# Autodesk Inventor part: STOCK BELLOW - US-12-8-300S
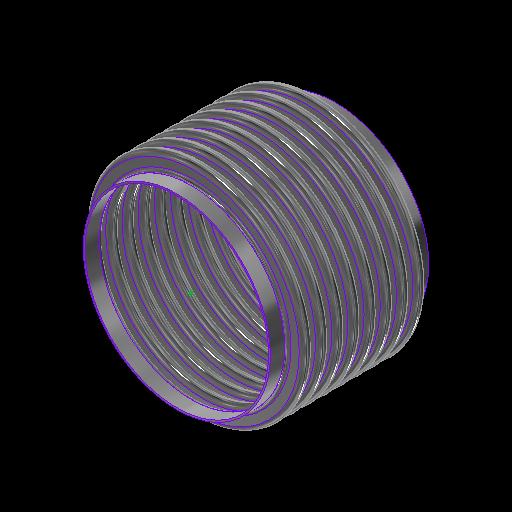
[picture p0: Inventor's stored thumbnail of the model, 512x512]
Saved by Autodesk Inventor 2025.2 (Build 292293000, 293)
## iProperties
Category: 16 GA (0.060 THICK)
RuleStatus: InUse
Created: 2024-01
Part Number: STOCK BELLOW - US-12-8-300S
Project: =STOCK BELLOWS: <Stock Number><SFILL>
Material: ASTM A240-304
Description: =STOCK BELLOWS: <Stock Number>, <SID_> I.D., <SOD_> O.D., <SPLY_> PLY, <Category>, <SNET_CONS> CONS.<PITCH_><STANGENT_> TANGENT<SFILL>
Document SubType Name: Sheet Metal
Designer: GS
Stock Number: U.S-12-8-300S
Surface Area: 14407.3 cm^2
Volume: 2167.04 cm^3
Sheet Metal Rule: Default
Appearance: STAINLESS STEEL
Mass: 17460.5 g
Density: 8.05729 g/cm^3
THK: 0.036
ID: 3.500
OD: 4.250
CONS_: 2
PITCH: 0.500
TANGENT: 0.500
BELLOWS_UPSET: 0.000
d79: 1.000
d82: 1.000
d83: 26.000
d84: 24.000
d174: 8
d214: 8
STHK_: 0.060
SID_: 12.750
SOD_: 15.250
SPITCH_: 1.125
STANGENT__: 1.000
SBELLOWS_UPSET_: 0.000
SDIFF_TAN: 1.000
d252: 2
d275: 2
d287: 0.050
d289: 0.500
d290: 0.000
SOD_NECK: 13
PLY: 1
PSET: 4.178
PBAR: 1.035
COUNTER: 1.500
NET_TUBE: 3.071
CONS: 2
S_CONS: 0
NET_CONS: 2
ID_M: 88.90 mm
OD_M: 107.95 mm
THK_M: 0.91 mm
ID_U: 3.500 in
OD_U: 4.250 in
THK_U: 0.036 in
TANGENT2: 0.500
TAN_TO_TAN: 1.000 in
d80: 2.571
d81: 10
SID: 2.375
SCONS_: 8
SPITCH: 0.250
STANGENT_: 1.000
SBELLOWS_UPSET: 0.000
SNET_CONS: 8
SS_CONS: 0
SCONS: 8
d190: 8
d191: 1
d192: 1
d193: 8
d194: 0
SIZE: 12.00
PRESSURE: 300
d230: 8
STANGENT: 4.000
SPLY_: 2
d233: 8
d234: 0
d263: 2
d265: 1
d268: 2
d269: 0
d286: 2
d288: 1
d291: 2
d292: 0
SREROLL: 0.750
BLETP: 0.000 ul
PRES_Copy: 85
MATTABLE: 20 GA (0.036 THICK)
PART_NUMBER: U.S-12-8-300S
PITCH_: =, <SPITCH_> PITCH,
CFILL: .
SFILL: .
MESH: ,
COMP: 1.57
EXT: 0.79
LAT: 0.33
ANG: 573
ASR: 7424
LSR: 26948
ANSR: 3175
PRES: 300
COMPM: 15.7
EXTM: 7.85
LATM: 3.30
ASRM: 1300.165
PRESM: 20.684
LSRM: 4719.403
ANSRM: 556.038
TEMPMIN: 20
TEMPMAX: 800
TEMPMINM: -7
TEMPMAXM: 427
WEIGHTM: 17.460
WEIGHT: 38.494
Author: GS
Keywords: 20 GA (0.036 THICK)
Comments: =STOCK BELLOW - <STOCK NUMBER>
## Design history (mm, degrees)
sketch "Sketch2"
  geometry: L1 (0, -177.245)-(0, 562.856) reference; L2 (45.364, 0)-(44.45, 0); L3 (48.082, -2.718)-(50.343, -2.718); L4 (48.082, -3.632)-(50.343, -3.632); L5 (50.343, -9.982)-(48.082, -9.982); L6 (50.343, -9.068)-(48.082, -9.068); L7 (45.364, -12.7)-(44.45, -12.7); L8 (48.082, 0)-(48.082, -12.7); L9 (50.343, -6.35)-(53.975, -6.35); L10 (44.45, 0)-(44.45, -12.7); L11 (20.376, 102.841)-(20.376, 101.926); L12 (58.262, 457.127)-(58.262, 349.177); L13 (58.262, 444.427)-(58.262, 336.477); L14 (93.133, -58.817)-(93.133, -71.517); L15 (118.746, -66.401)-(118.746, -66.401); L16 (50.343, -9.068)-(50.343, -9.982); L17 (48.082, -9.068)-(48.082, -9.982); L18 (48.082, -9.525)-(50.343, -9.525); L19 (53.975, 0)-(53.975, -12.7); L20 (-50.343, -9.068)-(-50.343, -9.982); L21 (-50.343, -2.718)-(-48.082, -2.718); L22 (-50.343, -3.632)-(-48.082, -3.632); L23 (-48.082, -9.068)-(-50.343, -9.068); L24 (-50.343, -9.525)-(-48.082, -9.525); L25 (-48.082, -9.982)-(-50.343, -9.982); L26 (-48.082, -9.068)-(-48.082, -9.982); L27 (-44.45, 0.653)-(-44.45, -12.047); L28 (-48.082, -6.35)-(-44.45, -6.35); L29 (-50.343, 0.653)-(-50.343, -12.7); L30 (-53.061, 0)-(-53.975, 0); L31 (-53.975, 0)-(-53.975, -12.7); L32 (-53.061, -12.7)-(-53.975, -12.7); A1 r 2.718 centre (48.082, 0) between (45.364, 0) and (48.082, -2.718); A2 r 3.632 centre (48.082, 0) between (44.45, 0) and (48.082, -3.632); A3 r 3.632 centre (50.343, -6.35) between (50.343, -9.982) and (50.343, -2.718); A4 r 2.718 centre (50.343, -6.35) between (50.343, -9.068) and (50.343, -3.632); A5 r 2.718 centre (48.082, -12.7) between (48.082, -9.982) and (45.364, -12.7); A6 r 3.632 centre (48.082, -12.7) between (48.082, -9.068) and (44.45, -12.7); A7 r 3.175 centre (50.343, -6.35) between (50.343, -9.525) and (53.518, -6.35); A8 r 3.175 centre (48.082, -12.7) between (48.082, -9.525) and (44.907, -12.7); A9 r 2.718 centre (-50.343, -12.7) between (-50.343, -9.982) and (-53.061, -12.7); A10 r 2.718 centre (-48.082, -6.35) between (-48.082, -9.068) and (-48.082, -3.632); A11 r 3.175 centre (-48.082, -6.35) between (-48.082, -9.525) and (-44.907, -6.35); A12 r 3.632 centre (-48.082, -6.35) between (-48.082, -9.982) and (-48.082, -2.718); A13 r 3.175 centre (-50.343, -12.7) between (-50.343, -9.525) and (-53.518, -12.7); A14 r 3.632 centre (-50.343, -12.7) between (-50.343, -9.068) and (-53.975, -12.7); A15 r 2.718 centre (-50.343, 0) between (-53.061, 0) and (-50.343, -2.718); A16 r 3.632 centre (-50.343, 0) between (-53.975, 0) and (-50.343, -3.632); 10 further points
  constraints: 62 end point, 38 point on circle, 20 tangent, 16 centre point, 12 parallel, 9 midpoint, 7 vertical, 6 coincident, 6 concentric, 6 point on line, 4 equal radius, 4 perpendicular, 3 horizontal, 1 collinear, 1 horizontal alignment, 10 other
  dimensions: "THK" = 0.9144 distance of L11.start L11.end; "ID" = 88.9 distance of L11.end point (20.376, 13.026); "OD" = 107.95 distance of L12.start L12.end; "PITCH" = 12.7 distance of L12.start L13.start; "TANGENT" = 12.7 distance of L14.start L14.end; "BELLOWS_UPSET" = 0 distance of L15.start L15.end; "d43" = 88.9 diameter of L10 L1 (= ID); "d44" = 107.95 diameter of L9.end L1 (= OD); "d45" = 0.9144 distance between parallel lines of L5 L6 (computed from THK, PLY); "d46" = 3.6322 radius of A3 (computed from PITCH, THK, PLY); "UPSET_PITCH" = 12.7 distance of L2.end L7.end (derived); "SIDEWALL_ANGLE" = 360 deg dimension on L3 L9 (derived); "CON_GAP" = 5.4356 distance of point (48.082, -9.068) point (48.082, -3.632) (derived); "TAN1" = 4.98728 dimension on A8 (derived); "TAN2" = 4.98728 dimension on A7 (derived); "LEG1" = 2.2606 distance of L18.start L18.end (derived); "d278" = 0.9144 distance between parallel lines of L25 L23 (derived); "d279" = 3.6322 radius of A12 (derived); "d280" = 12.7 distance of L30.end L31.end (derived); "d281" = 360 deg dimension on L21 L28 (derived); "d282" = 5.4356 distance of point (-50.343, -9.068) point (-50.343, -3.632) (derived); "d283" = 4.98728 dimension on A13 (derived); "d284" = 4.98728 dimension on A11 (derived); "d285" = 2.2606 distance of L24.start L24.end (derived); "d293" = 88.9 diameter of L27 L1 (derived); "d294" = 107.95 diameter of L31 L1 (derived)
  node "Sketch Rectangular Pattern1" dims "d31" = 25.4, "ID" = 88.9
  node "Sketch Rectangular Pattern2" dims "d39" = 25.4, "PITCH" = 12.7
revolve "CONS" stored, may be unused: angle "d48" = 90 deg
node "BELLOW MIDPLANE"
pattern_linear "Rectangular Pattern2" dims "d52" = 12.7 (= UPSET_PITCH)
sketch "Sketch5"
  geometry: C1 r 45.364 at (0, 0) reference; C2 r 44.45 at (0, 0) reference
extrude "TANGENT" new body sketch "Sketch5" distance "d53" = 12.7 (= TANGENT); taper "d54" = 0 deg
revolve "SAMETAN" stored, may be unused: angle "d65" = 90 deg
revolve "DIFFTAN" stored, may be unused: angle "d70" = 90 deg
sketch "Sketch9"
  geometry: L1 (53.319, 0)-(-53.319, 0) reference; L2 (0, -17.78)-(0, 17.78) reference; L3 (38.085, 0)-(-38.085, 0); L4 (38.085, -11.906)-(38.085, 11.906); L5 (25.385, -11.906)-(25.385, 11.906); L6 (13.15, 11.906)-(13.15, -11.906); L7 (-25.385, -11.906)-(-25.385, 11.906); L8 (-38.085, -11.906)-(-38.085, 11.906); L9 (37.291, -11.906)-(37.291, 11.906); L10 (38.085, -11.906)-(37.291, -11.906); L11 (38.085, 11.906)-(37.291, 11.906); L12 (13.546, 11.906)-(12.753, 11.906); L13 (12.753, 11.906)-(12.753, -11.906); L14 (12.753, -11.906)-(13.546, -11.906); L15 (13.546, -11.906)-(13.546, 11.906); L16 (-13.546, 11.906)-(-13.546, -11.906); L17 (-13.15, 11.906)-(-13.15, -11.906); L18 (-13.546, -11.906)-(-12.753, -11.906); L19 (-12.753, -11.906)-(-12.753, 11.906); L20 (-12.753, 11.906)-(-13.546, 11.906); L21 (-38.085, -11.906)-(-37.291, -11.906); L22 (-37.291, -11.906)-(-37.291, 11.906); L23 (-37.291, 11.906)-(-38.085, 11.906); L24 (-38.085, 11.906)-(-38.085, -11.906); L25 (38.085, -0.397)-(-38.085, -0.397); L26 (-38.085, -0.397)-(-38.085, 0.397); L27 (-38.085, 0.397)-(38.085, 0.397); L28 (38.085, 0.397)-(38.085, -0.397); L29 (-38.085, 11.906)-(38.085, 11.906); L30 (38.085, 11.906)-(38.085, 12.7); L31 (38.085, 12.7)-(-38.085, 12.7); L32 (-38.085, 12.7)-(-38.085, 11.906); L33 (38.085, -11.906)-(-38.085, -11.906); L34 (-38.085, -11.906)-(-38.085, -12.7); L35 (-38.085, -12.7)-(38.085, -12.7); L36 (38.085, -12.7)-(38.085, -11.906); 30 further points
  constraints: 68 end point, 13 midpoint, 13 parallel, 8 horizontal, 7 perpendicular, 6 equal length, 3 point on line, 2 vertical, 14 other
  dimensions: "d115" = 23.8125 distance of L4.start L4.end (derived); "d116" = 12.7 distance between parallel lines of L4 L5 (derived); "d117" = 12.23516 distance between parallel lines of L5 L6 (derived); "d125" = 38.53427 distance between parallel lines of L7 L6 (derived); "d127" = 12.7 distance between parallel lines of L8 L7 (derived); "d128" = 24.93516 distance between parallel lines of L6 L4 (derived); "d130" = 76.16943 distance between parallel lines of L8 L4 (derived); "RULER_THK" = 0.79375 distance between parallel lines of L4 L9; "d135" = 0.79375 distance of L13.end L14.end (derived); "d138" = 26.29911 distance of L13.end L16.end (derived); "d143" = 0.79375 distance of L22.end L8.end (derived); "d144" = 0.79375 distance between parallel lines of L27 L25 (derived)
extrude "RULER" join sketch "Sketch9" distance "d149" = 0.79375 (derived); taper "d150" = 0 deg
extrude "BARS" join sketch "Sketch9" distance "d151" = 0.79375 (derived); taper "d152" = 0 deg
pattern_linear "Rectangular Pattern4" dims "d155" = 26.29911 (derived)
sketch "Sketch13"
  geometry: L1 (93.149, -52.467)-(93.149, -77.867); L2 (164.973, 0)-(161.925, 0); L3 (164.973, -28.575)-(161.925, -28.575); L4 (185.007, -22.955)-(170.593, -22.955); L5 (185.007, -19.907)-(170.593, -19.907); L6 (185.007, -14.287)-(193.675, -14.288); L7 (170.593, -5.62)-(185.007, -5.62); L8 (170.593, 0)-(170.593, -28.575); L9 (161.925, 0)-(161.925, -28.575); L10 (58.254, -109.081)-(58.254, -496.431); L11 (58.254, -137.656)-(58.254, -525.006); L12 (58.254, -194.806)-(58.254, -582.156); L13 (58.254, -223.381)-(58.254, -610.731); L14 (58.254, -251.956)-(58.254, -639.306); L15 (58.254, -280.531)-(58.254, -667.881); L16 (58.254, -309.106)-(58.254, -696.456); L17 (58.254, -166.231)-(58.254, -553.581); L18 (20.376, 103.45)-(20.376, 101.926); L19 (170.593, -8.668)-(185.007, -8.668); L20 (0, -856.437)-(0, 263.431) reference; L21 (-38.735, 0)-(232.41, 0) reference; A1 r 5.62 centre (170.593, 0) between (164.973, 0) and (170.593, -5.62); A2 r 5.62 centre (170.593, -28.575) between (170.593, -22.955) and (164.973, -28.575); A3 r 8.668 centre (170.593, -28.575) between (170.593, -19.907) and (161.925, -28.575); A4 r 5.62 centre (185.007, -14.287) between (185.007, -19.907) and (185.007, -8.668); A5 r 8.668 centre (185.007, -14.287) between (185.007, -22.955) and (185.007, -5.62); A6 r 8.668 centre (170.593, 0) between (161.925, 0) and (170.593, -8.668); 6 further points; 1 other entity
  constraints: 38 end point, 15 point on circle, 9 tangent, 6 centre point, 6 parallel, 5 vertical alignment, 4 point on line, 4 vertical, 3 coincident, 3 concentric, 2 collinear, 2 equal radius, 1 horizontal, 1 perpendicular, 23 other
  dimensions: "SBELLOWS_UPSET_" = 0 distance of point (118.762, -66.401) point (118.762, -66.401); "STOTAL_THK_BELLOW__" = 3.048 distance between parallel lines of L4 L5 (derived); "d224" = 8.66775 radius of A5 (derived); "d225" = 28.575 distance of L2.end L3.end (derived); "SSIDEWALL_ANGLE_" = 360 deg dimension on L7 L6 (derived); "SSCON_GAP_" = 11.2395 distance of point (170.593, -19.907) point (170.593, -8.668) (derived); "d235" = 323.85 diameter of L9 L20 (derived); "d236" = 387.35 diameter of L6.end L20 (derived)
  node "Sketch Rectangular Pattern4" dims "d228" = 25.4
  node "Sketch Rectangular Pattern5" dims "d229" = 25.4
revolve "SBELLOW" stored, may be unused: angle "d197" = 90 deg
pattern_linear "Rectangular Pattern5" dims "d204" = 28.575 (derived)
revolve "STANGENT" stored, may be unused: angle "d240" = 90 deg
revolve "SSAMETAN" stored, may be unused: angle "d241" = 90 deg
revolve "SDIFFTAN" stored, may be unused: angle "d246" = 90 deg
revolve "INVCON" stored, may be unused: angle "d295" = 90 deg
pattern_linear "Rectangular Pattern6" dims "d298" = 12.7 (derived)
revolve "INVTANGENT" stored, may be unused: angle "d302" = 90 deg
revolve "INVSAMETAN" stored, may be unused: angle "d307" = 90 deg
revolve "INVDIFFTAN" stored, may be unused: angle "d312" = 90 deg
sketch "ID BELLOW MOUNT CALC"
  geometry: L1 (44.45, 0)-(38.1, 0); L2 (38.1, 0)-(38.1, 12.7); L3 (38.1, 12.7)-(44.45, 12.7); L4 (44.45, 12.7)-(44.45, 0); L5 (36.513, 12.7)-(35.598, 12.7); L6 (35.598, 12.7)-(35.598, 0); L7 (35.598, 0)-(36.513, 0); L8 (36.513, 0)-(36.513, 12.7); L9 (0, -2.54)-(0, 15.24) reference; L10 (-8.89, 0)-(53.34, 0) reference; 1 further point
  constraints: 16 end point, 5 parallel, 2 collinear, 2 horizontal, 2 perpendicular
  dimensions: "d314" = 12.7 distance of L5.end L6.end (derived); "d315" = 0.9144 distance of L5.start L5.end (derived); "IG" = 1.5875 distance between parallel lines of L2 L8; "PIPE_OD" = 88.9 diameter of L4 L9; "PIPE_WALL" = 6.35 distance of L2.end L3.end; "ID_MT_BELLOW" = 71.1962 diameter of L6 L9 (derived)
revolve "CFILL" stored, may be unused: angle "d320" = 90 deg
pattern_linear "Rectangular Pattern7" dims "d323" = 12.7 (derived)
revolve "SFILL" stored, may be unused: angle "d324" = 90 deg
pattern_linear "Rectangular Pattern8" dims "d327" = 28.575 (derived)
node "STOCK BELLOW MIDPLANE"
node "BELLOW"
sketch "Sketch6"
  geometry: L1 (-12.7, 45.364)-(0, 45.364); L2 (0, 45.364)-(0, 44.45); L3 (0, 44.45)-(-12.7, 44.45); L4 (-12.7, 44.45)-(-12.7, 45.364); L5 (10.16, 0)-(-60.96, 0) reference; L6 (-38.1, -89.422)-(-38.1, 153.44) reference; 1 further point
  constraints: 8 end point, 2 parallel, 1 horizontal, 1 perpendicular
  dimensions: "d61" = 12.7 distance of L2.end L3.end (derived); "d62" = 0.9144 distance of L1.end L2.end (derived); "d63" = 88.9 diameter of L3 L5 (derived); "d64" = 25.4 distance between parallel lines of L4 L6 (derived)
sketch "Sketch12"
  geometry: 1 further point
sketch "Sketch14"
  geometry: L1 (-25.4, 164.973)-(0, 164.973); L2 (0, 164.973)-(0, 161.925); L3 (0, 161.925)-(-25.4, 161.925); L4 (-25.4, 161.925)-(-25.4, 164.973); L5 (5.08, 0)-(-30.48, 0) reference; L6 (0, -32.995)-(0, 197.968) reference; 1 further point
  constraints: 8 end point, 2 parallel, 1 collinear, 1 horizontal, 1 perpendicular
  dimensions: "d237" = 3.048 distance of L3.end L1.start (derived); "d238" = 323.85 diameter of L3 L5 (derived); "d239" = 25.4 distance of L1.start L1.end (derived); "SOD_NECK" = 329.946 diameter of L1 L5 (derived)
sketch "Sketch15"
  geometry: L1 (-32.995, 0)-(197.968, 0) reference; L2 (161.925, -228.6)-(164.973, -228.6); L3 (164.973, -228.6)-(164.973, -254); L4 (164.973, -254)-(161.925, -254); L5 (161.925, -254)-(161.925, -228.6); L6 (0, -307.34)-(0, 66.04) reference; 1 further point
  constraints: 8 end point, 2 parallel, 1 horizontal, 1 perpendicular
  dimensions: "d205" = 25.4 distance of L4.end L2.start (derived); "d206" = 3.048 distance of L3.end L4.end (derived); "d207" = 323.85 diameter of L5 L6 (derived); "d208" = 228.6 distance between parallel lines of L1 L2 (derived)
node "TANGENT_"
node "SAME_TAN"
sketch "Sketch8"
  geometry: L1 (45.364, -25.4)-(44.45, -25.4); L2 (44.45, -25.4)-(44.45, -38.1); L3 (44.45, -38.1)-(45.364, -38.1); L4 (45.364, -38.1)-(45.364, -25.4); L5 (0, -48.26)-(0, 22.86) reference; L6 (-89.422, 0)-(153.44, 0) reference; 1 further point
  constraints: 8 end point, 2 parallel, 1 horizontal, 1 perpendicular
  dimensions: "d66" = 88.9 diameter of L2 L5 (derived); "TOTAL_THK_BELLOW" = 0.9144 distance of L2.end L3.end (derived); "d68" = 25.4 distance between parallel lines of L1 L6 (derived); "d69" = 12.7 distance of L1.end L2.end (derived)
node "DIFF_TAN"
node "Sketch Rectangular Pattern3" dims "d138" = 26.29911 (derived), "d141" = 25.4
node "SBELLOW_"
node "STANGENT_"
node "SSAME_TAN"
sketch "Sketch16"
  geometry: L1 (164.973, -228.6)-(161.925, -228.6); L2 (161.925, -228.6)-(161.925, -254); L3 (161.925, -254)-(164.973, -254); L4 (164.973, -254)-(164.973, -228.6); L5 (0, -307.34)-(0, 66.04) reference; L6 (-32.995, 0)-(197.968, 0) reference; 1 further point
  constraints: 8 end point, 2 parallel, 1 horizontal, 1 perpendicular
  dimensions: "SDIFF_TAN" = 25.4 distance of L3.end L1.start; "d243" = 3.048 distance of L2.end L3.end (derived); "d244" = 228.6 distance between parallel lines of L1 L6 (derived); "d245" = 323.85 diameter of L2 L5 (derived)
node "SDIFF_TAN"
body "Solid15"
sketch "Sketch17"
  geometry: L1 (53.975, 12.7)-(53.061, 12.7); L2 (53.061, 12.7)-(53.061, 0); L3 (53.061, 0)-(53.975, 0); L4 (53.975, 0)-(53.975, 12.7); L5 (0, -2.54)-(0, 15.24) reference; L6 (-10.795, 0)-(64.77, 0) reference; 2 further points
  constraints: 8 end point, 2 parallel, 1 horizontal, 1 midpoint, 1 perpendicular, 1 point on line
  dimensions: "INVTANGENT" = 12.7 distance of L3.end L1.start (derived); "d300" = 0.9144 distance of L1.start L1.end (derived); "d301" = 107.95 diameter of L4 L5 (derived)
body "Solid16"
sketch "Sketch18"
  geometry: L1 (53.975, -25.4)-(53.061, -25.4); L2 (53.061, -25.4)-(53.061, -38.1); L3 (53.061, -38.1)-(53.975, -38.1); L4 (53.975, -38.1)-(53.975, -25.4); L5 (-10.795, 0)-(64.77, 0) reference; L6 (0, -48.26)-(0, 22.86) reference; 1 further point
  constraints: 8 end point, 2 parallel, 1 horizontal, 1 perpendicular
  dimensions: "d303" = 25.4 distance between parallel lines of L1 L5 (derived); "d304" = 12.7 distance of L3.end L1.start (derived); "d305" = 0.9144 distance of L2.end L3.end (derived); "d306" = 107.95 diameter of L4 L6 (derived)
body "Solid17"
sketch "Sketch19"
  geometry: L1 (53.975, -25.4)-(53.061, -25.4); L2 (53.061, -25.4)-(53.061, -38.1); L3 (53.061, -38.1)-(53.975, -38.1); L4 (53.975, -38.1)-(53.975, -25.4); L5 (0, -48.26)-(0, 22.86) reference; L6 (-10.795, 0)-(64.77, 0) reference; 1 further point
  constraints: 8 end point, 2 parallel, 1 horizontal, 1 perpendicular
  dimensions: "d308" = 12.7 distance of L1.end L2.end (derived); "d309" = 107.95 diameter of L4 L5 (derived); "d310" = 0.9144 distance of L2.end L3.end (derived); "d311" = 25.4 distance between parallel lines of L1 L6 (derived)
body "Solid18"
body "Solid19"
body "Solid20"
other parameters: "BMPL" = -114.3, "PSET" = 106.1212 (computed from OD, THK, PLY) [user parameter], "PBAR" = 26.29911 (= 0.570796 x PITCH + OD - ID) [user parameter; used in 1 equation term], "COUNTER" = 15 [user parameter], "NET_TUBE" = 77.99823 (computed from CONS_, PBAR, TANGENT) [user parameter], "S_CONS" = 0 [user parameter; used in 1 equation term], "ID_M" = 88.9 (= ID) [user parameter], "OD_M" = 107.95 (= OD) [user parameter], "THK_M" = 0.9144 (= THK) [user parameter], "ID_U" = 88.9 (= ID) [user parameter], "OD_U" = 107.95 (= OD) [user parameter], "THK_U" = 0.9144 (= THK) [user parameter], "D_UNITS" = 0 [user parameter], "TANGENT2" = 12.7 [user parameter], "TAN_TO_TAN" = 25.4 [user parameter], "OD_NECK" = 90.7288 [user parameter], "d79" = 25.4, "d80" = 65.29823 [user parameter], "d82" = 25.4, "d83" = 660.4, "d84" = 609.6, "sa_0" = 4, "FRAME_THK" = 0.79375 [user parameter], "CON_FLAT" = 12.23516 [user parameter], "SID" = 60.325 [user parameter], "SPITCH" = 6.35 [user parameter], "STANGENT_" = 25.4 [user parameter], "SBELLOWS_UPSET" = 0 [user parameter], "SS_CONS" = 0 [user parameter], "STAN_TO_TAN_" = 228.6 [user parameter], "d100" = 3.048 [user parameter], "d191" = 25.4 [user parameter], "d194" = 0 [user parameter], "STANGENT" = 101.6 [user parameter], "d234" = 0 [user parameter], "SUPSET_PITCH_" = 28.575 [user parameter], "d269" = 0 [user parameter], "d287" = 1.27, "d289" = 12.7, "d290" = 0, "d292" = 0 [user parameter], "Thickness" = 3.048 (derived), "KFactor" = 4.4, "BendRadius" = 3.048 (derived), "BendReliefWidth" = 3.048 (derived), "BendReliefDepth" = 1.524 (derived), "CornerReliefSize" = 12.192 (derived), "SeamGap" = 0.00508, "MinimumRemnant" = 6.096 (derived), "TransitionRadius" = 3.048 (derived), "JacobiRadiusSize" = 3.048 (derived), "GapSize" = 3.048 (derived), "SREROLL" = 19.05 [user parameter], "CUR_STK_PITCH" = 28.575 [user parameter], "d328" = -114.3 (derived), "ASR" = 74240 [user parameter], "LSR" = 269480 [user parameter], "ANSR" = 31750 [user parameter], "BLETP" = 0 [user parameter], "ASRM" = 13001.6512 [user parameter], "PRESM" = 206.83949 [user parameter], "LSRM" = 47194.0324 [user parameter], "ANSRM" = 5560.3775 [user parameter], "TEMPMIN" = 2664.83333 [user parameter], "TEMPMAX" = 6998.16667 [user parameter], "TEMPMINM" = 2664.83333 [user parameter], "TEMPMAXM" = 6998.16667 [user parameter], "WEIGHT" = 174.60487 [user parameter], "WEIGHTM" = 0.1746 [user parameter]
